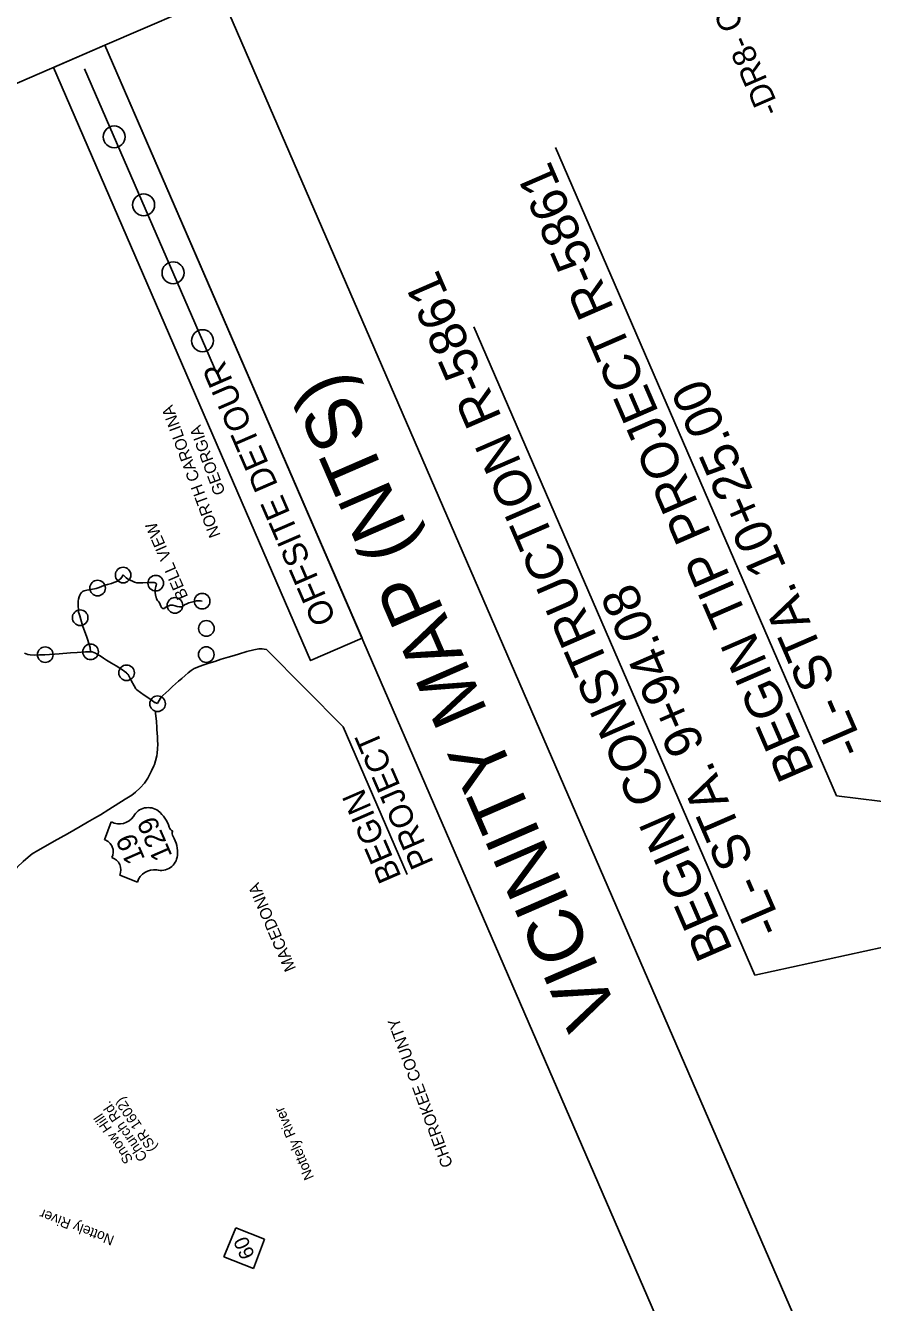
# Model space of a CAD drawing. Extents: x 442728 to 492797, y 479541 to 511293.
# Drawn here: x 475924 to 479354, y 487323 to 492495 of the extents above; entities that cross this region are included whole.
import ezdxf

# ---------------------------------------------------------------- set-up
doc = ezdxf.new("R2010")
doc.units = 0
for name, color, linetype in [('Default', 7, 'Continuous'), ('Old_Level_1', 7, 'Continuous'), ('Old_Level_22', 7, 'Continuous'), ('Old_Level_38', 7, 'Continuous'), ('Prop DSN Text', 7, 'Continuous'), ('Prop Grid Mask', 7, 'Continuous'), ('Prop Horizontal Alignment Station Label', 7, 'Continuous'), ('Prop PHM Text', 7, 'Continuous'), ('Prop PHM White Label Box', 7, 'Continuous')]:
    doc.layers.add(name, color=color, linetype=linetype)

msp = doc.modelspace()

# ---------------------------------------------------------------- linework, layer by layer
at = {"layer": 'Default'}
for p, q in [((476698, 491086.1), (476163, 492319.8)), ((479208.5, 489375.3), (478070.2, 492000.4)), ((478878.1, 488649.2), (477739.9, 491274.3)), ((477209.8, 489654.3), (476899.4, 489968.2)), ((476333.1, 489872.1), (476336.8, 489869.4)), ((477469.1, 489056.5), (477209.8, 489654.3)), ((479208.5, 489375.3), (481056.6, 489145.9)), ((476094.3, 489221.7), (476066.7, 489206.4)), ((478878.1, 488649.2), (481040.7, 489119.4))]:
    msp.add_line(p, q, dxfattribs=at)
for points in [[(476146.7, 490193.7), (476150.7, 490198.6), (476155.1, 490202.2), (476161.4, 490205.2), (476172.4, 490207.9), (476187.6, 490210.6), (476209.3, 490214.5), (476221.9, 490218.7), (476241.4, 490226.3), (476255.8, 490230.6), (476271.9, 490235.2), (476281.8, 490238.6), (476289.6, 490241.6), (476296.9, 490245.1), (476303.3, 490249.9), (476308.7, 490254.2), (476313.7, 490260.6), (476319.4, 490269.7)], [(476639.2, 490163.5), (476632.5, 490164.7), (476625.5, 490164.7), (476616.6, 490164.5), (476606.5, 490161.9), (476595.5, 490159.1), (476585.3, 490156.5), (476576.7, 490152.9), (476567.6, 490148), (476559.1, 490141.9), (476555.9, 490140.5), (476547.5, 490140.7), (476538.3, 490142.2), (476529.4, 490144.8), (476520.6, 490146.9), (476510.1, 490147), (476494.9, 490141), (476489.4, 490137.6), (476486, 490134.1), (476483.8, 490133.4), (476480.4, 490134), (476476.9, 490135.5), (476474.7, 490138.2), (476472, 490142.7), (476468.8, 490150), (476465.8, 490157), (476462.1, 490161.5), (476458, 490166.2), (476454.6, 490173.4), (476451.3, 490185), (476450.8, 490186.9), (476448.2, 490201.1), (476448.5, 490209.9), (476449.8, 490217.7), (476451.3, 490223.4), (476452.4, 490226.7), (476454.5, 490233.1), (476453.4, 490235.1), (476449.3, 490237.6), (476444.2, 490238.7), (476425.1, 490238.4), (476398.9, 490237.8), (476374, 490238.2), (476364.7, 490240.6), (476354.2, 490246.3), (476344, 490249.6), (476336.9, 490253.8), (476331.2, 490257.6), (476326.9, 490261.4), (476322.7, 490265.6), (476319.4, 490269.7)], [(476187.4, 489958.2), (476185.4, 489975.6), (476182.8, 489984.1), (476172.1, 490017.7), (476155.1, 490064.6), (476147.2, 490089), (476143, 490104.1), (476141, 490111.5), (476138.8, 490119.4), (476137.7, 490130.3), (476136.9, 490143.3), (476137.3, 490155), (476137.2, 490163.5), (476138.3, 490172.2), (476140.7, 490181.1), (476143.6, 490188), (476146.7, 490193.7)], [(476001.4, 489946.5), (476059.9, 489950.8), (476106.5, 489953.7), (476133.5, 489955.7), (476167.1, 489957.9), (476180.6, 489958.5), (476187.4, 489958.2)], [(476187.4, 489958.2), (476193.8, 489958), (476201, 489955.8), (476206.8, 489953), (476215.3, 489948), (476226.2, 489941.4), (476239.5, 489932.7), (476252.1, 489924.7), (476272, 489912.1), (476290.3, 489901), (476309.9, 489889.4), (476316.7, 489884.7), (476323.7, 489880), (476332.9, 489873.3)], [(476899.4, 489968.2), (476890.9, 489969.6), (476882.1, 489970.3), (476878, 489970.6), (476868.3, 489970.4), (476848.8, 489966.4), (476820.8, 489959), (476786.2, 489948.3), (476760, 489940.3), (476744.4, 489936.5), (476735.2, 489933.9), (476716.3, 489928), (476690.4, 489919)], [(475919.9, 489952.9), (475933.1, 489947.7), (475942.6, 489945.8), (475959, 489944.4), (475979.8, 489945.8), (476001.4, 489946.5)], [(476690.4, 489919), (476666.6, 489912), (476641.7, 489904.7)], [(476336.8, 489869.4), (476338.9, 489866.4), (476343.2, 489858.3), (476352.2, 489841.7), (476363.2, 489821), (476371.1, 489808.8), (476375, 489804.5), (476403.8, 489783.1), (476426.6, 489767.4), (476448.5, 489752.3)], [(476641.7, 489904.7), (476630.6, 489900.4), (476606.9, 489890.1), (476594.9, 489882.5), (476582.8, 489873.1), (476569.9, 489861.9), (476557.1, 489850.5), (476543.6, 489839.3), (476519.6, 489818.3), (476503.8, 489803.5), (476479.8, 489780.9), (476474.4, 489775.5), (476469.8, 489770), (476464.6, 489761.4), (476460.4, 489754.6), (476458.2, 489749.1)], [(476641.7, 489904.7), (476630.6, 489900.4), (476606.9, 489890.1), (476594.9, 489882.5), (476582.8, 489873.1), (476569.9, 489861.9), (476557.1, 489850.5), (476543.6, 489839.3), (476519.6, 489818.3), (476503.8, 489803.5), (476479.8, 489780.9), (476474.4, 489775.5), (476469.8, 489770), (476464.6, 489761.4), (476460.4, 489754.6), (476458.2, 489749.1)], [(476448.3, 489753.5), (476453.8, 489750.1), (476458.2, 489749.1)], [(476450.2, 489715), (476450, 489708.2), (476453.9, 489676.8), (476455.7, 489650.7), (476456.2, 489643.5), (476458.6, 489613.7), (476458.5, 489598.6), (476459.3, 489584.5), (476458.5, 489565), (476457.3, 489548.5), (476455.1, 489537.3), (476450.1, 489516.7), (476446.2, 489501.5), (476443.8, 489496.2)], [(476443.8, 489496.2), (476434.6, 489475.7), (476418.9, 489446.5), (476405.9, 489427), (476388, 489406.9), (476369.7, 489390.4), (476353.7, 489377.9), (476327.8, 489360.9), (476261.5, 489319.8), (476226.8, 489298), (476203.5, 489284.9), (476174.1, 489268.5), (476145, 489250.9), (476094.3, 489221.7)], [(476066.7, 489206.4), (476040, 489191.2), (476004.4, 489171.1), (475973.4, 489153.9), (475950.5, 489139.7), (475934.1, 489126.5), (475913.8, 489108.9), (475890.1, 489086), (475877.5, 489071.7), (475871.9, 489064.4), (475857.1, 489042.9), (475846.9, 489028.1), (475840.9, 489018.4), (475835.2, 489007.9), (475830.2, 488997.6), (475823.3, 488982.5), (475815, 488962.8), (475802.7, 488928.1)]]:
    msp.add_lwpolyline(points, dxfattribs=at)
for centre, radius in [((476282.7, 492043.9), 44.5), ((476402, 491768.7), 44.5), ((476521.4, 491493.4), 44.5), ((476640.7, 491218.2), 44.5), ((476319.1, 490269.3), 31.6), ((476451.3, 490236.3), 31.6), ((476215.6, 490216.6), 31.6), ((476529, 490146.3), 31.6), ((476639.2, 490163.5), 31.6), ((476145.1, 490096.5), 31.6), ((476656.2, 490052.9), 31.6), ((476003.4, 489946.7), 31.6), ((476187.4, 489958.2), 31.6), ((476655.8, 489947), 31.6), ((476332.9, 489873.3), 31.6), ((476458.5, 489747.9), 31.6)]:
    msp.add_circle(centre, radius, dxfattribs=at)
at = {"layer": 'Old_Level_1'}
for points in [[(479132.2, 487049), (476716.6, 492619.7), (476245.2, 492415.3), (478660.8, 486844.6)], [(478660.8, 486844.6), (476245.2, 492415.3), (472131.1, 490631.3), (474546.6, 485060.7)], [(478660.8, 486844.6), (476245.2, 492415.3), (472131.1, 490631.3), (474546.6, 485060.7)], [(478660.8, 486844.6), (476245.2, 492415.3), (472131.1, 490631.3), (474546.6, 485060.7)], [(478660.8, 486844.6), (476245.2, 492415.3), (472131.1, 490631.3), (474546.6, 485060.7)]]:
    msp.add_lwpolyline(points, close=True, dxfattribs=at)
at = {"layer": 'Prop Grid Mask'}
for p, q in [((476243.4, 489197.1), (476271.2, 489269.1)), ((476376.9, 489025.4), (476305.2, 489053.6)), ((476454.9, 489075.2), (476454.9, 489075.2))]:
    msp.add_line(p, q, dxfattribs=at)
msp.add_lwpolyline([(476245.2, 492415.3), (477286.8, 490013.4), (477078.6, 489923.1), (476037.1, 492325.1)], close=True, dxfattribs=at)
for centre, radius, start, end in [((476303.3, 489332.1), 70.6, 243.0256, 325.3656), ((476420.6, 489260.4), 67.1, 52.9078, 151.9677), ((476374.5, 489206.3), 138.1, 17.6313, 51.1919), ((476525.4, 489251.5), 19.6, 189.9394, 254.6384), ((476228, 489148.3), 51.2, 332.648, 72.4987), ((476537.2, 489222.8), 19.6, 150.0064, 217.0678), ((476401.2, 489143.2), 138.1, 355.8194, 29.3915), ((476472.2, 489140.1), 67.1, 255.049, 354.1035), ((476258.9, 489075.6), 51.2, 334.589, 73.4331), ((476444.7, 489005.4), 70.6, 81.6457, 163.5445)]:
    msp.add_arc(centre, radius, start, end, dxfattribs=at)
at = {"layer": 'Prop PHM White Label Box'}
for p, q in [((476775.6, 487625.7), (476727.6, 487508.3)), ((476892.2, 487579.7), (476775.6, 487625.7)), ((476847, 487461.1), (476892.2, 487579.7)), ((476727.6, 487508.3), (476847, 487461.1))]:
    msp.add_line(p, q, dxfattribs=at)

# ---------------------------------------------------------------- texts
at = {"layer": 'Default'}
for s, height, rotation, p in [('BEGIN TIP PROJECT R-5861', 150, 113.4424, (479120.3, 489476.2)), ('BEGIN CONSTRUCTION R-5861', 150, 113.4424, (478790, 488750.1)), ('-L- STA. 10+25.00', 150, 113.4424, (479326.7, 489565.7)), ('-L- STA. 9+94.08', 150, 113.4424, (478996.4, 488839.6)), ('PROJECT', 95, 113.4424, (477578.3, 489104.7)), ('BEGIN', 95, 113.4424, (477447.6, 489048)), ('Nottely River', 41.378, 113.4424, (477093.2, 487829.8)), ('Nottely River', 41.378, 159.3386, (476286.5, 487591.4))]:
    msp.add_text(s, height=height, rotation=rotation, dxfattribs=at).set_placement(p)
at = {"layer": 'Old_Level_22'}
for s, height, rotation, p in [('NORTH CAROLINA', 47.289, 110.3232, (476714.5, 490430.9)), ('GEORGIA', 47.29, 110.3232, (476734.1, 490603.5)), ('BELL VIEW', 47.29, 113.4424, (476583.2, 490181.9)), ('MACEDONIA', 47.29, 113.4424, (477020.1, 488675.8)), ('CHEROKEE COUNTY', 47.289, 110.3232, (477655.8, 487880)), ('(SR 1602)', 41.38, 124.0299, (476458.6, 487949.8)), ('Church Rd.', 41.38, 124.0299, (476419.8, 487911.2)), ('Snow Hill', 41.38, 124.0299, (476361.4, 487901.9))]:
    msp.add_text(s, height=height, rotation=rotation, dxfattribs=at).set_placement(p)
at = {"layer": 'Old_Level_38'}
msp.add_text('VICINITY MAP (NTS)', height=221.436, rotation=113.4424, dxfattribs=at).set_placement((478328.2, 488493.1))
at = {"layer": 'Prop DSN Text'}
for s, height, rotation, p in [('-DR8- COBB CIR.', 94.918, 113.4424, (478983.2, 492151.7)), ('129', 81.22, 113.5056, (476519.6, 489132.8)), ('19', 81.22, 113.5056, (476409.3, 489119.4))]:
    msp.add_text(s, height=height, rotation=rotation, dxfattribs=at).set_placement(p)
at = {"layer": 'Prop Horizontal Alignment Station Label'}
msp.add_text('OFFSITE DETOUR', height=98.469, rotation=113.4424, dxfattribs=at).set_placement((477183.6, 490090))
at = {"layer": 'Prop PHM Text'}
msp.add_text('60', height=59.66, rotation=113.4424, dxfattribs=at).set_placement((476853.9, 487514.3))

doc.saveas('drawing.dxf')
